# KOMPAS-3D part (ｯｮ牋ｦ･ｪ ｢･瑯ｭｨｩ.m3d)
File: created 20.08.2015 19:35:12, last saved 28.07.2016 12:55:00.
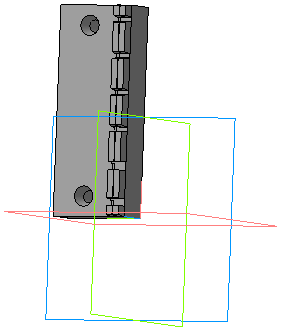
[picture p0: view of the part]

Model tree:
1. Эскиз:1
2. Операция выдавливания:1
     Расстояние 1 = 8
3. Эскиз:2
4. Операция выдавливания:2
     Расстояние 1 = 1
5. Эскиз:3
6. Операция выдавливания:3
     Расстояние 1 = 2.5; Угол 1 = 8
7. Эскиз:4
8. Вырезать элемент выдавливания:1
     Расстояние 1 = 20
9. Эскиз:5
10. Вырезать элемент выдавливания:2
     Расстояние 1 = 3; Угол 1 = 19
11. Скругление:1
     Радиус = 1
12. Скругление:2
     Радиус = 1
13. Скругление:3
     Радиус = 1
14. Эскиз:6
15. Эскиз:7
16. Вырезать элемент выдавливания:3
     Расстояние 1 = 2.5
17. Эскиз:8
18. Вырезать элемент выдавливания:4
     Расстояние 1 = 42
19. Операция выдавливания:4
     Расстояние 1 = 0.8; Расстояние 2 = 1.5
20. Скругление:4
     Радиус = 1
21. Скругление:5
     Радиус = 1
22. Эскиз:9
23. Вырезать элемент выдавливания:5
     Толщина стенки 1 = 0.1; Расстояние 1 = 2.5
